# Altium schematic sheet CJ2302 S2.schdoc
size 127 x 101 mm
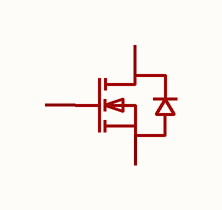
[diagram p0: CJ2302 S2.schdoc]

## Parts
Q?  cj2302 s2  [SOT-23-3_L3.0-W1.7-P0.95-LS2.9-BR]  (value not drawn)

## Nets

Not connected (* = marked no-connect by the designer): Q? 1(G) 2(S) 3(D)

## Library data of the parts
Q? = cj2302 s2: 数量:1个N沟道;漏源电压(Vdss):20V;连续漏极电流(Id):2.1A;导通电阻(RDS(on)):115mΩ@2.5V;耗散功率(Pd):350mW;阈值电压(Vgs(th)):1.2V;; Manufacturer: CJ(江苏长电/长晶); AddInBom: yes; ModelId: 89cb27a44ab2466697082bb9fd73a7d0; ModelName: SOT-23-3L_L2.9-W1.6-H1.1-LS2.8-P0.95; ModelTransform: 114.173,110.236,0,90,0,0,0,0,0; Number: 1个N沟道; Drain to Source Voltage: 20V; Current - Continuous Drain(Id): 2.1A; Pd - Power Dissipation: 350mW; Gate Threshold Voltage (Vgs(th)): 1.2V; Gate Charge(Qg): 10nC@4.5V; Input Capacitance(Ciss): 300pF; Reverse Transfer Capacitance (Crss@Vds): 80pF; Type: N沟道; Output Capacitance(Coss): 120pF; Vgs: ±8V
